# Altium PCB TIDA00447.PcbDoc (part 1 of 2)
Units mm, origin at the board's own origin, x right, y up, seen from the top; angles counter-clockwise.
Board outline 98 x 65 mm, 2 copper layers (Top Layer, Bottom Layer); 127 components, 100 nets, 389 pads, 331 vias.
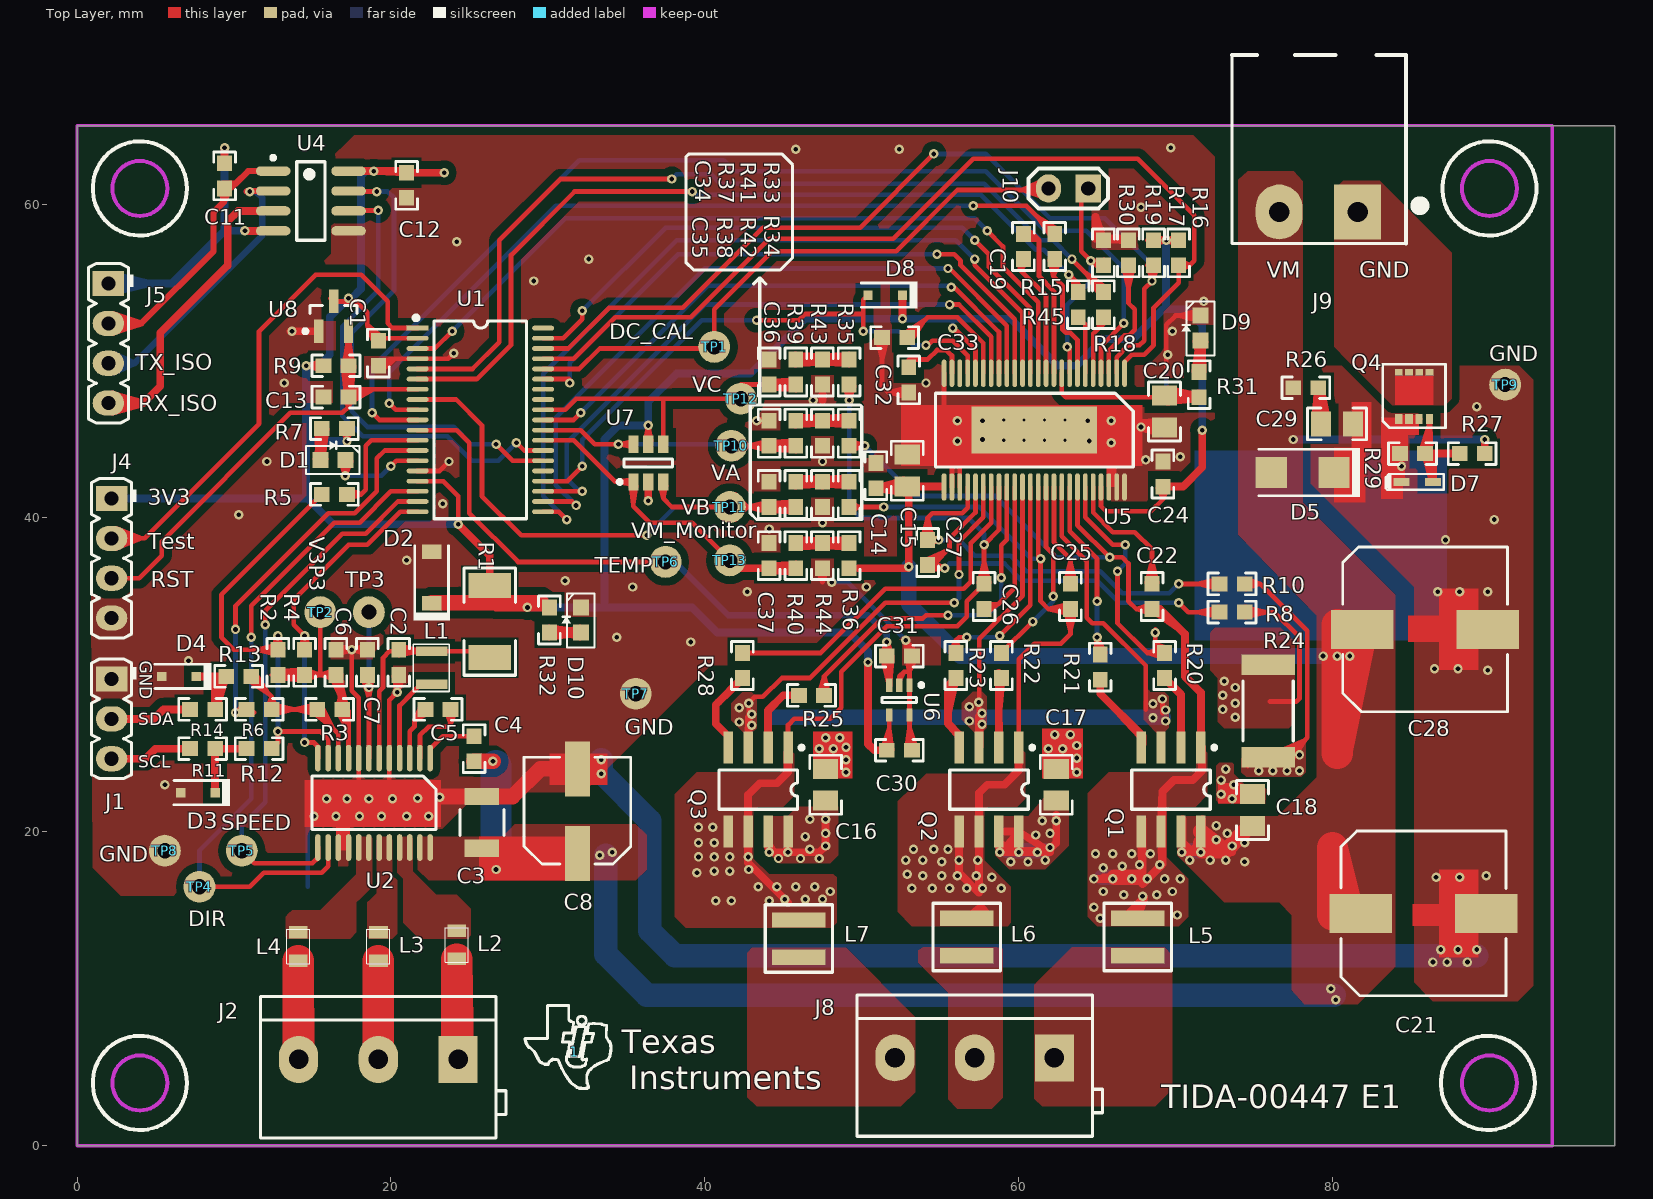
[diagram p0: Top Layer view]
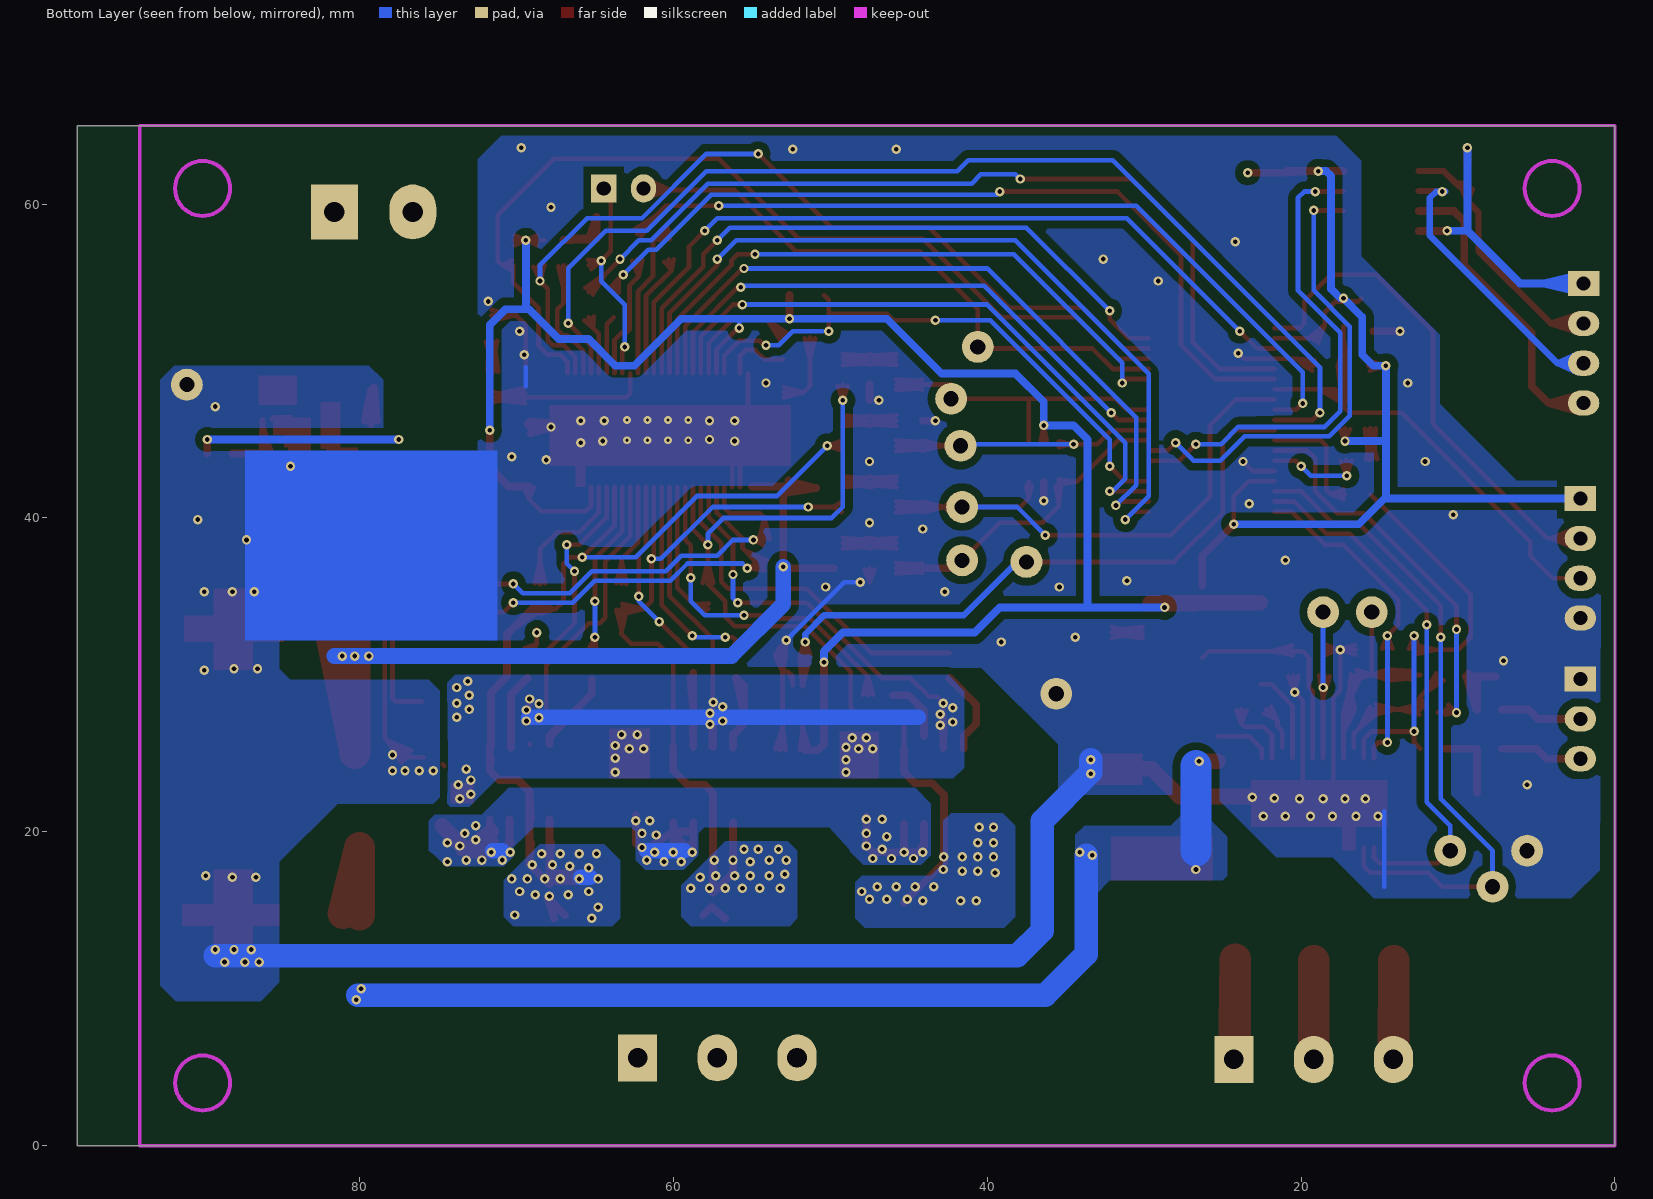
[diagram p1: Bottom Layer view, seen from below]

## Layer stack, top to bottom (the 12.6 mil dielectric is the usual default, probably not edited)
Top Layer: signal copper 0.0356
Dielectric: dielectric 0.32, FR-4, Dk 4.8
Bottom Layer: signal copper 0.0356

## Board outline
0,0 98,0 98,65 0,65

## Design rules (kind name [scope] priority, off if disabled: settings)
Clearance Clearance_1 [(InNamedPolygon('Bottom Layer-GND') OR InNamedPolygon('Bottom Layer-GND2') OR InNamedPolygon('Bottom Layer-GND') OR InNamedPolygon('Top Layer-gnd') OR InNamedPolygon('Top Layer-GND2'))] p1: gap=0.5
Clearance [All] p2: gap=0.2
ComponentClearance [All] p1 off: gap=0.254 collisioncheckmode=3 verticalgap=0.254 showdistances=FALSE
PolygonConnect PolygonConnect_1 [(InPadClass('All Pads'))] p1 off: connectstyle=Relief reliefconductorwidth=0.5 reliefentries=4 polygonreliefangle="90 Angle" airgapwidth=0.5
PolygonConnect [All] p2: connectstyle=Direct reliefconductorwidth=0.254 reliefentries=4 polygonreliefangle="90 Angle" airgapwidth=0.254
RoutingVias [All] p1: holewidth=0.3 width=0.6 viastyle="Through Hole" minholewidth=0.3 minwidth=0.6 maxholewidth=0.3 maxwidth=0.6
SilkscreenOverComponentPads [All] p1: minsilkscreentomaskgap=0.254
SolderMaskExpansion [All] p1: expansion=0.102
Width [All] p1: maxlimit=2 minlimit=0.203 preferedwidth=0.254
26 further rules are at their usual default settings.

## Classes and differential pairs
component class TIDA00447_MCU+DRV10983: C1 C2 C3 C4 C5 C6 C7 C8 C11 C12 C13 D1 D2 D3 D4 J1 J2 J4 J5 L1 L2 L3 L4 R1 R2 R3 R4 R5 R6 R7 R9 R11 R12 R13 R14 TP1 TP2 TP3 TP4 TP5 U1 U2 U4 U8
component class TIDA00447_DRV8303: C8 C14 C15 C16 C17 C18 C19 C20 C21 C22 C24 C25 C26 C27 C29 C30 C31 C32 C33 C34 C35 C36 C37 D5 D7 D8 D9 D10 J8 J9 J10 L5 L6 L7 Q1 Q2 Q3 Q4 R8 R10 R15 R16 R17 R18 R19 R20 R21 R22 R23 R24 R25 R26 R27 R28 R29 R30 R31 R32 R33 R34 R35 R36 R37 R38 R39 R40 R41 R42 R43 R44 R45 TP6 TP7 TP8 TP9 TP10 TP11 TP12 TP13 U5 U6 U7
component class Header: J1 J4 J5

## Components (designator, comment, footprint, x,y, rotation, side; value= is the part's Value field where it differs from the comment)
1 "" TIBUG4 31.7,6 r0 top
C1 "C1608X8R1E104K" 0603 19.2,50.5 r270 top
C2 "C1608X5R1A106M" 0603 20.5,30.8 r270 top
C3 "GRM32ER61H106KA12L" 1210_280 25.8,20.6 r270 top
C4 "C1608X7R1H104K" 0603 25.3,25.3 r90 top
C5 "C1608X7R1H104K" 0603 23,27.8 r180 top
C6 "C1608X5R0J105K" 0603 16.5,30.8 r90 top
C7 "C1608X5R0J105K" 0603 18.5,30.8 r270 top
C8 "APXA6R3ARA101MF60G" CAPSMT_62_F60 31.9,21.3 r90 top (schematic designator C28)
C11 "C1608X8R1E104K" 0603 9.4,61.8 r90 top
C12 "C1608X8R1E104K" 0603 21,61.2 r270 top
C13 "C1608X7R1H222K" 0603 16.5,47.7 r180 top
C14 "06035C104KAT2A" 0603 50.9,42.7 r90 top
C15 "C2012X5R1H475K125AB" 0805_HV 52.9,43.016 r90 top
C16 "C2012X7R1H105K125AB" 0805_HV 47.7,23 r270 top
C17 "C2012X7R1H105K125AB" 0805_HV 62.4,23 r270 top
C18 "C2012X7R1H105K125AB" 0805_HV 74.9,21.4 r270 top
C19 "C1608X8R1H223K" 0603 60.3,57.3 r270 top
C20 "C2012X7R1V225K085AC" 0805_HV 69.3,46.784 r90 top
C21 "EEHZA1V271P" SM_RADIAL_10BMM 85.8,14.8 r0 top
C22 "06035C104KAT2A" 0603 68.5,35 r90 top
C24 "C0603X104K8RACTU" 0603 69.2,42.8 r90 top
C25 "06035C104KAT2A" 0603 63.3,35 r90 top
C26 "06035C104KAT2A" 0603 57.8,35 r270 top
C27 "C1608C0G1H102J" 0603 54.2,37.8 r90 top
C28 "EEHZA1V271P" SM_RADIAL_10BMM 85.9,32.9 r0 top
C29 "08055C103JAT2A" 0805_HV 80.284,46 r0 top
C30 "C1608C0G1E103J" 0603 52.4,25.2 r0 top
C31 "C1608C0G1E103J" 0603 52.4,31.2 r0 top
C32 "C1608X5R1E105K080AC" 0603 53,48.8 r270 top
C33 "C1608X5R1E105K080AC" 0603 52.1,51.5 r180 top
C34 "C1608X5R1A474K" 0603 44.1,45.4 r90 top
C35 "C1608X5R1A474K" 0603 44.1,41.5 r90 top
C36 "C1608X5R1A474K" 0603 44.1,49.3 r90 top
C37 "C1608X5R1A474K" 0603 44.1,37.6 r90 top
D1 "D_LED_603" LED603 16.3,43.7 r180 top
D2 "MMSZ5227B-7-F" SOD-123 22.6,36.2 r90 top
D3 "MMSZ5232BS-7-F" sod-323 7.7,22.5 r180 top
D4 "MMSZ5232BS-7-F" sod-323 6.5,29.9 r180 top
D5 "SMAJ30CA" SMA 78.1,42.9 r180 top
D7 "BZT52C16T-7" SOD-523 85.4,42.3 r180 top
D8 "GBLC03-LF-T7" sod-323 51.5,54.2 r180 top
D9 "D_LED_603" LED603 71.603,52.082 r270 top
D10 "D_LED_603" LED603 32.103,33.482 r270 top
J1 "61300311121" WURTH_61300311121 2.2,27.2 r270 top
J2 "ED120/3DS" CONN_ED120_3DS 19.2,5.5 r270 top
J4 "61300411121" WURTH_61300411121 2.2,37.43 r270 top
J5 "61300411121" WURTH_61300411121 2,51.13 r270 top
J8 "ED120/3DS" CONN_ED120_3DS 57.2,5.6 r270 top
J9 "ED1817-ND" "CN2P/5.0 -11*12" 79.1,59.5 r180 top
J10 "JUMPER_2X100MIL" HDR100_1X2 64.44,61 r180 top
L1 "CB2518T470K" IND_CB2518 22.6,30.45 r270 top
L2 "MPZ2012S300A" MPZ2012 24.2,12.8 r270 top
L3 "MPZ2012S300A" MPZ2012 19.2,12.7 r270 top
L4 "MPZ2012S300A" MPZ2012 14.1,12.7 r270 top
L5 "XFL4015-471MEC" XFL4015 67.6,13.3 r270 top
L6 "XFL4015-471MEC" XFL4015 56.7,13.3 r270 top
L7 "XFL4015-471MEC" XFL4015 46,13.2 r270 top
Q1 "CSD88539ND" SO-G8/E2.5 69.7,22.7 r180 top
Q2 "CSD88539ND" SO-G8/E2.5 58.1,22.7 r180 top
Q3 "CSD88539ND" SO-G8/E2.5 43.4,22.7 r180 top
Q4 "CSD17304Q3" TRANS_NexFET_Q3 85.2,47.8 r90 top
R1 "CRCW20100000Z0EF" 2010 26.3,33.4 r270 top
R2 "CRCW06034K75FKEA" 0603 12.8,30.8 r270 top
R3 "CRCW06034K75FKEA" 0603 16.1,27.8 r0 top
R4 "CRCW06034K75FKEA" 0603 14.5,30.8 r270 top
R5 "RC0603JR-070RL" 0603 16.4,41.5 r180 top
R6 "RC0603JR-070RL" 0603 11.6,27.8 r0 top
R7 "CRCW0603270RJNEA" 0603 16.4,45.7 r0 top
R8 "CRCW06030000Z0EA" 0603 73.6,34 r0 top
R9 "CRCW060347K0JNEA" 0603 16.5,49.7 r180 top
R10 "CRCW06030000Z0EA" 0603 73.6,35.8 r0 top
R11 "CRCW0603100RJNEA" 0603 8,25.3 r0 top
R12 "CRCW0603100RJNEA" 0603 11.6,25.3 r0 top
R13 "CRCW0603100RJNEA" 0603 10.3,29.9 r0 top
R14 "CRCW0603100RJNEA" 0603 8,27.8 r0 top
R15 "CRCW060327R0JNEA" 0603 62.3,57.3 r270 top
R16 "CRCW060310K0FKEA" 0603 70.2,56.9 r90 top
R17 "CRCW060310K0FKEA" 0603 68.6,56.9 r90 top
R18 "CRCW060327R0JNEA" 0603 65.4,53.6 r270 top
R19 "CRCW06031R00FKEA" 0603 67,56.9 r270 top
R20 "CRCW06033R90JNEA" 0603 69.3,30.6 r270 top
R21 "CRCW06033R90JNEA" 0603 65.2,30.5 r270 top
R22 "CRCW06033R90JNEA" 0603 58.9,30.6 r270 top
R23 "CRCW06033R90JNEA" 0603 56,30.6 r270 top
R24 "CSRN2512FK10L0" 2512 75.9,27.7 r90 top
R25 "CRCW06033R90JNEA" 0603 46.8,28.7 r180 top
R26 "CRCW06033R30JNEA" 0603 78.3,48.3 r0 top
R27 "CRCW06033K00JNEA" 0603 88.9,44.1 r0 top
R28 "CRCW06033R90JNEA" 0603 42.4,30.6 r270 top
R29 "CRCW060310K0FKEA" 0603 85.1,44.1 r0 top
R30 "CRCW060310K0FKEA" 0603 65.4,56.9 r270 top
R31 "CRCW06031K00FKEA" 0603 71.5,48.5 r270 top
R32 "CRCW06031K00FKEA" 0603 30.1,33.5 r90 top
R33 "RC0603FR-0730KL" 0603 49.2,45.4 r270 top
R34 "RC0603FR-0730KL" 0603 49.2,41.5 r270 top
R35 "RC0603FR-0730KL" 0603 49.2,49.3 r270 top
R36 "RC0603FR-0730KL" 0603 49.2,37.6 r270 top
R37 "CRCW06031K00FKEA" 0603 45.8,45.4 r270 top
R38 "CRCW06031K00FKEA" 0603 45.8,41.5 r270 top
R39 "CRCW06031K00FKEA" 0603 45.8,49.3 r270 top
R40 "CRCW06031K00FKEA" 0603 45.8,37.6 r270 top
R41 "RC0603FR-073K48L" 0603 47.5,45.4 r90 top
R42 "RC0603FR-073K48L" 0603 47.5,41.5 r90 top
R43 "RC0603FR-073K48L" 0603 47.5,49.3 r90 top
R44 "RC0603FR-073K48L" 0603 47.5,37.6 r90 top
R45 "CRCW060327R0JNEA" 0603 63.8,53.6 r270 top
TP1 "DC_CAL" TESTPOINT 40.6,50.9 r270 top
TP2 "V3P3" TESTPOINT 15.5,34 r270 top
TP3 "V1P8" TESTPOINT 18.6,34 r270 top
TP4 "DIR" TESTPOINT 7.8,16.5 r270 top
TP5 "SPEED" TESTPOINT 10.5,18.8 r270 top
TP6 "TEMP" TESTPOINT 37.5,37.2 r270 top
TP7 "GND" TESTPOINT 35.6,28.8 r270 top
TP8 "GND" TESTPOINT 5.6,18.8 r270 top
TP9 "GND" TESTPOINT 91,48.5 r180 top
TP10 "VA" TESTPOINT 41.7,44.6 r270 top
TP11 "VB" TESTPOINT 41.6,40.7 r270 top
TP12 "VC" TESTPOINT 42.3,47.6 r270 top
TP13 "VM_Monitor" TESTPOINT 41.6,37.3 r270 top
U1 "MSP430G2544_DA_3" IC-TSSOP38-DA 25.7,46.25 r0 top
U2 "DRV10983PWP" PWP0024B_N 18.925,21.85 r270 top
U4 "ISO7421D" D0008A_N 14.9,60.2 r0 top
U5 "DRV8303DCA" DCA0048A_N 61,45.6 r270 top
U6 "LMT84DCK" DCK0005A_N 52.4,28.4 r270 top
U7 "TPD4S009DBVRG4" DBV0006A_N 36.4,43.5 r90 top
U8 "TLV803SDBZR" DBZ0003A_N 16.35,52.85 r90 top

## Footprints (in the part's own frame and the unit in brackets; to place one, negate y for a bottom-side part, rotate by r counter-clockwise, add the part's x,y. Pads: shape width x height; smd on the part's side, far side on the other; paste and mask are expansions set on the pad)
0603 [mm] "0603 from SM-752 data"
  rect 1x0.95 smd: 1(-0.8,0) 2(0.8,0)
  silkscreen extent -1.52,-0.69 1.52,0.69, body extent -0.87,-0.47 0.87,0.47, height 0.85
0805_HV [mil] "0805 with 30mil clearance between pads"
  rect 50x63 smd: 1(-40,0) 2(40,0)
  silkscreen extent -74,-40 74,40, body extent -43,-29 43,29, height 43
1210_280 [mm] "SMD, 2-Leads, Body 3.6x2.8mm, Height 2.8mm"
  rect 1.1x2.2 smd: 1(-1.65,0) 2(1.65,0)
  silkscreen extent -0.84,-1.4 0.84,1.4, body extent -1.8,-1.4 1.8,1.4, height 2.8
2010 [mm] "Chip Capacitor, Body 5.08x2.54mm, IPC Medium Density"
  rect 1.6x2.7 smd: 1(-2.3,0) 2(2.3,0)
  silkscreen extent -3.42,-1.65 3.42,1.65, body extent -2.73,-1.45 2.73,1.45, height 1.66
2512 [mm] "Chip Resistor, Body 6.3x3.2mm, IPC Medium Density"
  rect 1.3x3.4 smd: 1(-2.95,0) 2(2.95,0)
  silkscreen extent -1.9,-1.6 1.9,1.6, body extent -3.22,-1.67 3.22,1.67, height 0.71
CAPSMT_62_F60 [mm] "6.3 x 5.7mm:  Chemi-Con F60"
  rect 3.5x1.6 smd: 1(-2.688,0.012) 2(2.712,0.012)
  silkscreen extent -3.35,-3.39 3.45,3.41, body extent -3.4,-3.4 3.45,3.42, height 6
"CN2P/5.0 -11*12" [mm]
  rect 3x3.5 hole 1.3: 1(-2.5,0)
  oval 3x3.5 hole 1.3: 2(2.5,0)
  silkscreen extent -6.57,-10 5.5,2
CONN_ED120_3DS [mm] "ONSHORE"
  rect 3x2.5 hole 1.25: 1(0,5.08)
  oval 3x2.5 hole 1.25: 2(0,0) 3(0,-5.08)
  silkscreen extent -4,-7.5 5,8.14, body extent -4.13,-7.55 5.05,8.14, height 13.1
D0008A_N [mm] "SOIC, 8-Leads, Body 4.9x3.9mm, Pitch 1.27mm, IPC Medium Density"
  oval 2.2x0.6 smd: 1(-2.4,1.905) 2(-2.4,0.635) 3(-2.4,-0.635) 4(-2.4,-1.905) 5(2.4,-1.905) 6(2.4,-0.635) 7(2.4,0.635) 8(2.4,1.905)
  silkscreen extent -2.52,-2.5 0.9,2.88, body extent -2,-2.5 2,2.5, height 1.75
DBV0006A_N [mm] "SOT23, 6-Leads, Body 2.9x1.6mm, Pitch 0.95mm, Lead Span 2.8mm, IPC Medium Density"
  rect 1.1x0.65 smd: 1(-1.2,0.95) 2(-1.2,0) 3(-1.2,-0.95) 4(1.2,-0.95) 5(1.2,0) 6(1.2,0.95)
  silkscreen extent -1.32,-1.55 0.25,1.95, body extent -0.87,-1.52 0.87,1.53, height 1.45
DBZ0003A_N [mm] "SOT23, 3-Leads, Body 2.9x1.3mm, Pitch 0.95mm, Lead Span 2.4mm, IPC Medium Density"
  rect 1.5x0.6 smd: 1(-0.95,0.95) 2(-0.95,-0.95) 3(0.95,0)
  silkscreen extent -1.07,-1.5 0.7,1.92, body extent -0.7,-1.52 0.7,1.52, height 1.12
DCA0048A_N [mm] "TSSOP, 48-Leads, Body 12.6x6.2mm (max), Pitch 0.50mm, IPC Medium Density"
  oval 1.75x0.3 smd: 1(-3.625,5.75) 2(-3.625,5.25) 3(-3.625,4.75) 4(-3.625,4.25) 5(-3.625,3.75) 6(-3.625,3.25) 7(-3.625,2.75) 8(-3.625,2.25) 9(-3.625,1.75) 10(-3.625,1.25) 11(-3.625,0.75) 12(-3.625,0.25) 13(-3.625,-0.25) 14(-3.625,-0.75) 15(-3.625,-1.25) 16(-3.625,-1.75) 17(-3.625,-2.25) 18(-3.625,-2.75) 19(-3.625,-3.25) 20(-3.625,-3.75) 21(-3.625,-4.25) 22(-3.625,-4.75) 23(-3.625,-5.25) 24(-3.625,-5.75) 25(3.625,-5.75) 26(3.625,-5.25) 27(3.625,-4.75) 28(3.625,-4.25) 29(3.625,-3.75) 30(3.625,-3.25) 31(3.625,-2.75) 32(3.625,-2.25) 33(3.625,-1.75) 34(3.625,-1.25) 35(3.625,-0.75) 36(3.625,-0.25) 37(3.625,0.25) 38(3.625,0.75) 39(3.625,1.25) 40(3.625,1.75) 41(3.625,2.25) 42(3.625,2.75) 43(3.625,3.25) 44(3.625,3.75) 45(3.625,4.25) 46(3.625,4.75) 47(3.625,5.25) 48(3.625,5.75)
  rect 3x8 smd: 49(0,0)
  silkscreen extent -2.35,-6.3 2.35,6.3, body extent -4.06,-6.25 4.06,6.25, height 0.98
DCK0005A_N [mm] "SOT353, 5-Leads, Body 2x1.3mm, Pitch 0.65mm, Lead Span 2.1mm, IPC Medium Density"
  rect 0.85x0.4 smd: 1(-0.95,0.65) 2(-0.95,0) 3(-0.95,-0.65) 4(0.95,-0.65) 5(0.95,0.65)
  silkscreen extent -1.07,-1.1 0.15,1.53, body extent -0.7,-1.07 0.7,1.08, height 1.1
HDR100_1X2 [mm]
  rect 1.6x1.8 hole 0.9: 1(0,0)
  oval 1.6x1.8 hole 0.9: 2(2.54,0)
  silkscreen extent -1.27,-1.27 3.81,1.27
IC-TSSOP38-DA [mm]
  rect 1.4x0.3 smd: 1(-4,5.85)
  oval 1.4x0.3 smd: 2(-4,5.2) 3(-4,4.55) 4(-4,3.9) 5(-4,3.25) 6(-4,2.6) 7(-4,1.95) 8(-4,1.3) 9(-4,0.65) 10(-4,0) 11(-4,-0.65) 12(-4,-1.3) 13(-4,-1.95) 14(-4,-2.6) 15(-4,-3.25) 16(-4,-3.9) 17(-4,-4.55) 18(-4,-5.2) 19(-4,-5.85) 20(4,-5.85) 21(4,-5.2) 22(4,-4.55) 23(4,-3.9) 24(4,-3.25) 25(4,-2.6) 26(4,-1.95) 27(4,-1.3) 28(4,-0.65) 29(4,0) 30(4,0.65) 31(4,1.3) 32(4,1.95) 33(4,2.6) 34(4,3.25) 35(4,3.9) 36(4,4.55) 37(4,5.2) 38(4,5.85)
  silkscreen extent -4.25,-6.3 2.95,6.65
IND_CB2518 [mm] "TAIYO YUDEN"
  rect 0.6x2 smd: 1(-1.05,0) 2(1.05,0)
  silkscreen extent -1.49,-1.17 1.51,1.13, body extent -1.35,-1 1.35,1, height 2
LED603 [mil]
  rect 40x40 smd: 1(-32.2,-0.1) 2(30.8,-0.1)
  silkscreen extent -67,-47 68,35
MPZ2012 [mm] "MURATA"
  rect 0.8x1.2 smd: 1(-0.9,0) 2(0.9,0)
  silkscreen extent -1.1,-0.72 1.1,0.72, body extent -1.1,-0.72 1.1,0.72, height 1.05
PWP0024B_N [mm] "TSOP, 24-Leads, Body 7.9x4.5mm (max), Pitch 0.65mm, IPC Medium Density"
  oval 1.7x0.35 smd mask+0.085: 1(-2.85,3.575) 2(-2.85,2.925) 3(-2.85,2.275) 4(-2.85,1.625) 5(-2.85,0.975) 6(-2.85,0.325) 7(-2.85,-0.325) 8(-2.85,-0.975) 9(-2.85,-1.625) 10(-2.85,-2.275) 11(-2.85,-2.925) 13(2.85,-3.575) 14(2.85,-2.925) 15(2.85,-2.275) 16(2.85,-1.625) 17(2.85,-0.975) 18(2.85,-0.325) 19(2.85,0.325) 20(2.85,0.975) 21(2.85,1.625) 22(2.85,2.275) 23(2.85,2.925) 24(2.85,3.575)
  oval 1.7x0.35 smd: 12(-2.85,-3.575)
  silkscreen extent -1.7,-3.95 1.7,3.95, body extent -3.21,-3.9 3.21,3.9, height 0.98
SM_RADIAL_10BMM [mm] "Nichicon 10x10"
  rect 4x2.5 smd: 1(-4,0) 2(4,0)
  silkscreen extent -5.25,-5.25 5.25,5.25, body extent -5.26,-5.26 5.26,5.26, height 10.5
SMA [mm] "Molded Diode, 2-Leads, Body 4.3x2.6mm, IPC Medium Density, based on OnSemi component dimensions and land pattern"
  rect 2x2 smd: 1(-2,0) 2(2,0)
  silkscreen extent -3.66,-1.57 2.79,1.57, body extent -2.6,-1.3 2.6,1.3, height 2.42
SO-G8/E2.5 [mm]
  rect 0.6x2.05 smd: 1(-1.915,-2.666) 2(-0.645,-2.666) 3(0.625,-2.666) 4(1.895,-2.666) 5(1.895,2.684) 6(0.625,2.684) 7(-0.645,2.684) 8(-1.915,2.684)
  silkscreen extent -2.89,-2.79 2.49,1.26
SOD-123 [mm] "On Semi recommended land pattern"
  rect 0.915x1.22 smd: 1(-1.637,0) 2(1.637,0)
  silkscreen extent -2.74,-1.17 2.03,1.17, body extent -1.93,-0.9 1.93,0.9, height 1.35
sod-323 [mm] "NXP recommended land pattern"
  rect 0.6x0.6 smd paste-0.05: 1(-1.1,0) 2(1.1,0)
  silkscreen extent -2.06,-0.86 1.53,0.86, body extent -1.3,-0.67 1.3,0.68, height 1.1
SOD-523 [mm]
  rect 1x0.5 smd: 1(-1,0) 2(1,0)
  silkscreen extent -1.7,-0.5 2,0.5
TESTPOINT [mil]
  round 80 hole 37.99: 1(0,0)
TIBUG4 [mm]
  silkscreen extent -3.15,-2.35 2.32,2.93
TRANS_NexFET_Q3 [mm] "TI recommended land pattern (nominal) M0143-01"
  rect 0.63x0.5 smd mask+0.076: 1(-1.49,0.975) 2(-1.49,0.325)
  rect 0.63x0.45 smd mask+0.076: 3(-1.49,-0.325) 4(-1.49,-0.975)
  rect 0.41x0.5 smd mask+0.076: 5(1.49,-0.975) 6(1.49,-0.325) 7(1.49,0.325) 8(1.49,0.975)
  Top Layer region: -0.615,-1.225 1.285,-1.225 1.285,1.225 -0.615,1.225
  silkscreen extent -2.05,-2 2,2, body extent -1.76,-1.7 1.66,1.7, height 1.11
WURTH_61300311121 [mm] "Header, 2.54mm, 3x1, TH"
  rect 1.6x2 hole 0.9: 1(-2.54,0)
  oval 1.6x2 hole 0.9: 2(0,0) 3(2.54,0)
  silkscreen extent -3.81,-1.27 3.81,1.6, body extent -3.81,-1.27 3.81,1.27, height 8.54
WURTH_61300411121 [mm] "Header, 2.54mm, 4x1, TH"
  rect 1.6x2 hole 0.9: 1(-3.81,0)
  oval 1.6x2 hole 0.9: 2(-1.27,0) 3(1.27,0) 4(3.81,0)
  silkscreen extent -5.08,-1.27 5.08,1.6, body extent -5.08,-1.27 5.08,1.27, height 8.54
XFL4015 [mm] "SMD, 2-Leads, Body 4x4mm"
  rect 0.98x3.4 smd: 1(-1.185,0) 2(1.185,0)
  silkscreen extent -2.15,-2.15 2.15,2.15, body extent -2.15,-2.15 2.15,2.15, height 1.6

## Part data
C1 C11 C12: "CAP, CERM, 0.1 μF, 25 V, +/- 10%, X8R, 0603"
C2: "CAP, CERM, 10 μF, 10 V, +/- 20%, X5R, 0603"
C3: "CAP, CERM, 10 μF, 50 V, +/- 10%, X5R, 1210"
C4 C5 C14 C22 C25 C26: "CAP, CERM, 0.1 μF, 50 V, +/- 10%, X7R, 0603"
C6 C7: "CAP, CERM, 1 μF, 6.3 V, +/- 10%, X5R, 0603"
C8: "CAP, AL, 100uF, 6.3V, +/-20%, 0.027 ohm, SMD"
C13: "CAP, CERM, 2200 pF, 50 V, +/- 10%, X7R, 0603"
C15: "CAP, CERM, 4.7 μF, 50 V, +/- 10%, X5R, 0805"
C16 C17 C18: "CAP, CERM, 1 μF, 50 V, +/- 10%, X7R, 0805"
C19: "CAP, CERM, 0.022 μF, 50 V, +/- 10%, X8R, 0603"
C20: "CAP, CERM, 2.2 μF, 35 V, +/- 10%, X7R, 0805"
C21 C28: "CAP, AL, 270 μF, 35 V, +/- 20%, 20 ohm, SMD"
C24: "CAP, CERM, 0.1 μF, 10 V, +/- 10%, X7R, 0603"
C27: "CAP, CERM, 1000 pF, 50 V, +/- 5%, C0G/NP0, 0603"
C29: "CAP, CERM, 0.01 μF, 50 V, +/- 5%, X7R, 0805"
C30 C31: "CAP, CERM, 0.01 μF, 25 V, +/- 5%, C0G/NP0, 0603"
C32 C33: "CAP, CERM, 1 μF, 25 V, +/- 10%, X5R, 0603"
C34 C35 C36 C37: "CAP, CERM, 0.47 μF, 10 V, +/- 10%, X5R, 0603"
D1 D9 D10: "Diode, LED, [Color], x-V, 20-mA, y-mcd"
D2: "Diode, Zener, 3.6 V, 500 mW, SOD-123"
D3 D4: "Diode, Zener, 5.6 V, 200 mW, SOD-323"
D5: "Diode, TVS, Bi, 30 V, 400 W, SMA"
D7: "Diode, Zener, 16 V, 300 mW, SOD-523"
D8: "Diode, TVS, Uni, 3.3 V, 350 W, SOD-323"
J1: "Header, 2.54 mm, 3x1, Gold, TH"
J2 J8: "TERMINAL BLOCK 5.08MM VERT 3POS, TH"
J4 J5: "Header, 2.54 mm, 4x1, Gold, TH"
J9: library part ED120/2DS, "TERMINAL BLOCK 5.08MM VERT 2POS, TH"
J10: "Header, Male 2-pin, 100mil spacing,"
L1: "Inductor, Wirewound, Ferrite, 47 μH, 0.11 A, 1.235 ohm, SMD"
L2 L3 L4: library part MPZ2012S101A, "Ferrite Bead, 100 ohm @ 100 MHz, 4 A, 0805"
L5 L6 L7: "Inductor, Shielded, Composite, 470 nH, 3.5 A, 0.0076 ohm, SMD"
Q1 Q2 Q3: "MOSFET, N-CH, 60 V, 6.3 A, SO-8"
Q4: "MOSFET, N-CH, 30 V, 56 A, SON 3.3x3.3mm"
R1: "RES, 0, 5%, 0.75 W, 2010"
R2 R3 R4: "RES, 4.75 k, 1%, 0.1 W, 0603"
R5 R6 R8 R10: "RES, 0, 5%, 0.1 W, 0603"
R7: "RES, 270, 5%, 0.1 W, 0603"
R9: "RES, 47 k, 5%, 0.1 W, 0603"
R11 R12 R13 R14: "RES, 100, 5%, 0.1 W, 0603"
R15 R18 R45: "RES, 27, 5%, 0.1 W, 0603"
R16 R17 R29 R30: "RES, 10.0 k, 1%, 0.1 W, 0603"
R19: "RES, 1.00, 1%, 0.1 W, 0603"
R20 R21 R22 R23 R25 R28: "RES, 3.9, 5%, 0.1 W, 0603"
R24: "RES, 0.01, 1%, 2 W, 2512"
R26: "RES, 3.3, 5%, 0.1 W, 0603"
R27: "RES, 3.0 k, 5%, 0.1 W, 0603"
R31 R32 R37 R38 R39 R40: "RES, 1.00 k, 1%, 0.1 W, 0603"
R33 R34 R35 R36: "RES, 30.0 k, 1%, 0.1 W, 0603"
R41 R42 R43 R44: "RES, 3.48 k, 1%, 0.1 W, 0603"
TP1 TP2 TP3 TP4 TP5 TP6 TP7 TP8 TP9 TP10 TP11 TP12 TP13: library part TESTPOINT, "TEST POINT.  No entry in BOM."
U1: "Imported"
U2: "12- to 24-V, Three-Phase, Sensorless BLDC Motor Driver, PWP0024B"
U4: "1 Mbps Dual Channels, 1 / 1, Digital Isolator, 3.3 V / 5 V, -40 to +105 degC, 8-pin SOIC (D), Green (RoHS & no Sb/Br)"
U5: "THREE PHASE PRE-DRIVER WITH DUAL CURRENT SHUNT AMPLIFIERS, DCA0048A"
U6: "Analog Temperature Sensors with Class-AB Output, DCK0005A"
U7: "ESD Solution for High-Speed Differential Interface, 4 Channels, -40 to +85 degC, 6-pin SOT-23 (DBV), Green (RoHS & no Sb/Br)"
U8: "3-Pin Voltage Supervisors with Active-Low, Open-Drain Reset, DBZ0003A"

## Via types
v1: diameter 0.6, hole 0.3, Top Layer to Bottom Layer, 323 vias
v2: diameter 0.5, hole 0.2, Top Layer to Bottom Layer, tented top, 8 vias

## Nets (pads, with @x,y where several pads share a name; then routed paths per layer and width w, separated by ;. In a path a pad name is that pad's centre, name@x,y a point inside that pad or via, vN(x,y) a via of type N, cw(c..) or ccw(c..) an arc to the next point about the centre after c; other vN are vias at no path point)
3V3_ISO: C11.1 J5.2 U4.1 | length 27.5
  Top Layer w0.4: J5.2@2,52.4 4.1,52.4 ; J5.2@2.2,52.4 4.1,52.4 ; J5.2@2.295,51.808 4.1,52.4 ; J5.2@2.295,52.992 4.1,52.4 ; C11.1@9.129,60.926 9.4,60.2 ; C11.1@9.348,61.295 10.1,61.3 ; C11.1@9.4,60.975 9.4,60.2 ; C11.1@9.4,61.025 10.1,61.3 ; C11.1@9.546,60.792 10.1,61.3 ; C11.1@9.671,60.926 9.4,60.2 ; U4.1@11.7,62.105 10.905,62.105 ; U4.1@12.5,62.105 10.905,62.105 ; 4.1,52.4 8.7,57 8.7,59.5 9.4,60.2 ; 9.4,60.2 C11.1@9.4,61 9.7,61.3 10.1,61.3 ; 10.1,61.3 10.905,62.105
GND: C1.2 C2.2 C3.1 C6.2 C7.1 C8.2 C12.2 C13.2 C14.2 C15.2 C20.1 C21.2 C24.2 C28.2 C29.2 C30.2 C31.2 C32.2 C33.2 C34.2 C35.2 C36.2 C37.2 D2.2 D3.2 D4.2 D5.1 D7.2 D9.1 D10.1 J1.1 J4.4 Q4.1 Q4.2 Q4.3 R10.2 R19.1 R24.1 R29.1 R30.1 R41.1 R42.1 R43.1 R44.1 TP7.1 TP8.1 TP9.1 U1.4 U1.15 U2.5 U2.8 U2.15 U2.16 U4.5 U5.24 U5.26 U5.27 U5.46 U5.47 U5.48 U5.49 U6.1 U6.2 U6.5 U7.2 U8.1 | length 311.7
  Top Layer w0.3: C6.2@16.5,31.6 v1@17.6,31.6 ; C6.2@16.548,31.279 v1@17.6,31.6 ; C6.2@16.548,31.921 v1@17.6,31.6 ; C6.2@16.6,31.6 v1@17.6,31.6 ; 17.95,22.35 U2.8@17.95,24.7 17.95,28.55 17.5,29 17.5,31.5 v1@17.6,31.6 ; 17.95,22.95 U2.8@17.95,24.025 ; U2.8@17.95,25.375 17.95,26.45 ; C7.1@18.441,31.28 v1@17.6,31.6 ; C7.1@18.441,31.92 v1@17.6,31.6 ; C7.1@18.5,31.6 v1@17.6,31.6 ; C1.2@19.123,50.041 20.25,50.15 ; C1.2@19.2,49.725 20.25,50.15 ; C1.2@19.364,49.444 20.25,50.15 ; 19.9,22.5 U2.5@19.9,24.7 19.9,28.4 v1(20.4,28.9) ; 19.9,22.95 U2.5@19.9,24.025 ; U2.5@19.9,25.375 19.9,26.45 ; C2.2@20.176,29.956 v1(20.4,28.9) ; C2.2@20.4,29.6 v1(20.4,28.9) ; C2.2@20.5,29.975 v1(20.4,28.9) ; C2.2@20.815,29.897 v1(20.4,28.9) ; U1.4@21.15,50.15 20.25,50.15 ; U1.15@21.7,43 23.1,43 ; U1.15@22.25,43 23.1,43 ; U1.4@22.25,50.15 23.3,50.15 ; v1(23.7,43.6) 23.1,43 ; v1(24,50.5) 23.65,50.15 U1.4@21.7,50.15 20.25,50.15 ; R44.1@47.181,36.715 47.5,35.9 ; R44.1@47.5,36.775 47.5,35.9 ; R44.1@47.5,36.8 47.5,35.9 ; R44.1@47.819,36.715 47.5,35.9 ; C33.2@50.977,51.462 51.3,50.125 C33.2@51.623,51.462 ; C33.2@51.3,51.5 51.3,48.4 51.7,48 ; U6.2@52.4,29.35 52.4,29.9 ; C15.2@52.684,43.784 52.75,43.85 55.95,43.85 ; C30.2@52.85,25.209 53.05,26.596 ; C31.2@52.85,31.188 53.05,30.2 ; C31.2@52.857,31.134 v1(52.8,32.2) ; C32.2@52.959,47.678 51.7,48 ; C32.2@52.959,48.322 51.7,48 ; C32.2@53,48 51.7,48 ; 53.05,26.125 U6.5@53.05,27.225 ; U6.5@53.05,27.675 53.05,28.775 U6.1@53.05,29.125 ; U6.1@53.05,29.575 53.05,30.2 ; C15.2@53.054,43.847 54.61,43.85 ; C15.2@53.065,44.032 54.61,43.85 ; C15.2@53.084,43.547 54.61,43.85 ; C15.2@53.098,44.214 54.61,43.85 ; C30.2@53.175,25.2 53.05,26.596 ; C15.2@53.196,44.499 54.61,43.85 ; C30.2@53.2,25.2 53.05,25.35 U6.5@53.05,27.45 U6.1@53.05,29.35 53.05,30.2 ; C31.2@53.458,31.359 v1(52.8,32.2) ; C31.2@53.487,31.108 53.05,30.2 ; C30.2@53.493,25.266 53.05,26.596 ; U5.24@55.225,49.2 U5.24@55.25,49.225 55.25,46.15 55.8,45.6 U5.49@58.5,45.6 ; 55.25,47.45 U5.24@55.25,48.5 ; U5.26@55.75,41.975 55.75,43.65 ; U5.26@55.75,42.7 55.75,43.65 ; U5.27@56.25,41.975 56.25,43.65 ; U5.27@56.25,42.7 56.25,43.65 ; U5.49@59.834,44.261 U5.49@58.5,45.6 ; U5.49@59.834,46.939 U5.49@58.5,45.6 ; U5.49@60.04,44.505 U5.49@58.5,45.6 ; U5.49@60.04,46.695 U5.49@58.5,45.6 ; U5.49@60.199,44.772 U5.49@58.5,45.6 ; U5.49@60.199,46.428 U5.49@58.5,45.6 ; U5.49@60.31,45.056 U5.49@58.5,45.6 ; U5.49@60.31,46.144 U5.49@58.5,45.6 ; U5.49@60.373,45.351 U5.49@58.5,45.6 ; U5.49@60.373,45.849 U5.49@58.5,45.6 ; U5.49@60.39,45.6 U5.49@58.5,45.6 ; U5.49@61,45.6 U5.49@58.5,45.6 ; 69.4,49.6 69.4,52.3 70,52.9 D9.1@71.6,52.9 70.192,52.9 ; D9.1@71.554,52.545 70.192,52.9 ; D9.1@71.554,53.255 70.192,52.9 ; R10.2@74.4,35.8 75.4,35.8 ; R10.2@74.425,35.8 75.4,35.8 ; R10.2@74.479,35.48 75.4,35.8 ; R10.2@74.479,36.12 75.4,35.8 ; R24.1@74.6,24.2 R24.1@74.7,24.3 ; R24.1@75.9,24.75 77.15,24.75 78.4,26 78.4,32.8 75.4,35.8 ; R24.1@76.687,25.175 78.247,25.847 ; R24.1@76.83,24.91 78.247,25.847 ; R24.1@76.95,24.75 78.247,25.847 ; R24.1@77.088,24.605 78.247,25.847 ; R24.1@77.326,24.42 78.247,25.847 ; D7.2@84.3,42.4 D7.2@84.4,42.3 ; 19.8,49.7 19.288,49.387 19.8,49.7 ; 19.8,49.7 19.288,50.013 19.8,49.7 ; 19.8,49.7 C1.2@19.2,49.7 19.8,49.7 ; 19.8,49.7 20.25,50.15 ; U6.2@52.4,29.575 52.4,29.9 ; U6.2@52.4,29.575 52.4,29.9 ; U6.2@52.4,29.575 52.7,30.2 ; 52.4,29.9 52.7,30.2 ; 52.7,30.2 53.05,30.2 ; v1(52.8,32.2) 53.175,31.2 53.05,30.2 ; v1(52.8,32.2) 53.2,31.8 ; U6.1@53.05,29.125 53.05,28.025 U6.1@53.05,29.125 ; 53.05,30.2 53.05,31.05 C31.2@53.2,31.2 ; C31.2@53.2,31.2 53.2,31.8 ; C31.2@53.2,31.2 53.2,31.8 ; 53.2,31.8 53.513,31.288 53.2,31.8 ; 53.2,31.8 52.887,31.288 53.2,31.8 ; 55.75,43.65 55.95,43.85 ; 55.95,43.85 56.45,43.85 ; 56.25,43.65 56.45,43.85 ; 56.45,43.85 56.75,43.85 U5.49@58.5,45.6
  Top Layer w0.4: Q4.2@84.875,46.31 Q4.3@85.525,46.31 Q4.2@84.875,46.31
  Top Layer w0.5: v1@13.6,51.9 v1(13.7,51.9) ; U7.2@36.4,42.075 v1(36.4,41.1) U7.2@36.4,42.3 ; R43.1@47.5,48.475 47.5,47.5 R43.1@47.5,48.5 ; R30.1@65.019,57.8 R19.1@67,57.725 ; 66.716,45.984 C20.1@69.3,45.984 ; C20.1@69.062,45.39 66.986,45.984 ; C20.1@69.135,45.768 66.986,45.984 ; C20.1@69.139,46.153 66.986,45.984 ; R29.1@84.3,44.073 D7.2@84.4,42.3 R29.1@84.3,44.074 ; R29.1@84.3,44.1 84.3,42.4 R29.1@84.3,44.4 ; v1(13.7,51.9) U8.1@15.4,51.9 v1(13.7,51.9) ; 64.9,57.8 R30.1@65.4,57.725 ; 64.9,57.8 R30.1@65.4,57.725 ; 64.9,57.8 66.4,57.8 ; 64.9,57.8 64.9,59.2 R30.1@65.4,57.725 ; R30.1@65.4,57.725 R19.1@67,57.7 66.5,57.7 66.4,57.8 ; R30.1@65.4,57.725 66.4,57.8 ; 66.4,57.8 R19.1@67,57.725 ; 66.4,57.8 R19.1@67,57.725 ; 66.4,57.8 R19.1@67,57.725 ; v1(43.3,46.2) C34.2@44.1,46.2 v1(43.3,46.2)
  Top Layer w1: 20.75,22.25 C3.1@25.8,22.25 27.75,22.25 ; v1@21.7,22.25 C3.1@25.25,22.25 ; C3.1@26.35,22.25 27.75,22.25 ; C8.2@31.888,24.012 29.512,24.012 27.75,22.25
  Bottom Layer w0.3: 14.7,16.5 14.7,21.3 ; v1(48.1,35.9) 49.1,35.9 v1(52.8,32.2) ; 69.4,48.4 69.4,49.6
  Bottom Layer w1.5: v1(33.4,24.6) 33.4,23.8 36.5,20.7 36.5,13.7 38.1,12.1 89.2,12.1
  other v1: 86.4,11.7 87.3,11.7 88.6,11.7 86.9,12.5 88,12.5 89.2,12.5 86.6,17.1 88.1,17.1 89.8,17.2 15.1,21 16.5,21 18,21 19.4,21 21,21 22.4,21 15.9,22.1 17.2,22.1 18.6,22.1 20.1,22.1 21.7,22.15 23.1,22.2 5.6,23 33.4,23.7 75.3,23.9 76.2,23.9 77.1,23.9 77.9,23.9 77.9,24.9 89.9,30.3 86.5,30.4 88,30.4 7.1,30.9 17.5,31.6 39.1,32.1 34.4,32.4 42.7,35.3 86.7,35.3 88.1,35.3 89.9,35.3 35.4,35.6 50.3,35.6 31.1,36 21,37.3 87.2,38.6 44.1,39.3 47.5,39.7 90.3,39.9 10.3,40.2 23.3,40.9 84.4,43.3 12.1,43.6 47.5,43.6 68.1,43.7 70.3,43.9 65.9,44.8 56.1,44.9 64.5,44.9 57.7,45 67.8,45.8 56.1,46.2 57.7,46.2 64.4,46.2 65.9,46.2 89.2,47.1 46.9,47.5 13.2,48.6 54.1,48.6 69.5,50.4 69.8,51.9 71.8,53.8 29.1,55.1 32.6,56.5 24.2,57.6 67.8,59.8 45.8,63.5 52.4,63.5 69.7,63.6
  other v2: 59.05,44.95 60.35,44.95 61.65,44.95 62.95,44.95 59.05,46.25 60.35,46.25 61.65,46.25 62.95,46.25
GND_IN: J9.1 Q4.5 Q4.6 Q4.7 Q4.8
GVDD: C20.2 R31.2 U5.9 | length 56.1
  Top Layer w0.3: U5.9@62.75,48.5 62.75,47.95 ; U5.9@62.75,49.225 62.75,47.95 ; C20.2@69.439,47.617 70.992,47.491 ; C20.2@69.444,47.315 70.992,47.491 ; C20.2@69.461,47.985 R31.2@71.08,47.931 ; C20.2@69.491,47.617 R31.2@71.08,47.931 ; C20.2@69.499,48.284 R31.2@71.08,47.931 ; C20.2@69.513,47.979 70.992,47.491 ; C20.2@69.576,47.328 R31.2@71.08,47.931 ; C20.2@69.634,48.255 70.992,47.491 ; R31.2@71.462,47.377 70.125,47.7 ; R31.2@71.462,48.023 70.125,47.7 ; 62.75,47.95 63,47.7 R31.2@71.5,47.7 70.125,47.7 ; C20.2@69.463,47.615 70.125,47.7 ; C20.2@69.463,47.615 70.125,47.7 ; C20.2@69.463,47.615 70.125,47.7 ; C20.2@69.465,47.8 71.003,47.7 ; C20.2@69.465,47.8 70.125,47.7 ; C20.2@69.465,47.8 71.003,47.7 ; C20.2@69.465,47.8 70.125,47.7 ; C20.2@69.465,47.8 R31.2@71.08,47.931 ; C20.2@69.465,47.8 70.125,47.7 ; C20.2@69.465,47.8 70.992,47.491 ; C20.2@69.518,47.977 70.125,47.7 ; C20.2@69.518,47.977 70.125,47.7 ; C20.2@69.518,47.977 70.125,47.7 ; C20.2@69.572,47.327 70.125,47.7 ; C20.2@69.572,47.327 70.125,47.7 ; C20.2@69.572,47.327 70.125,47.7 ; C20.2@69.707,48.22 70.125,47.7 ; C20.2@69.707,48.22 70.125,47.7 ; C20.2@69.707,48.22 70.125,47.7 ; 71.003,47.7 69.464,47.615 71.003,47.7 ; 71.003,47.7 69.488,47.984 71.003,47.7 ; 71.003,47.7 69.51,47.317 71.003,47.7 ; 71.003,47.7 69.572,48.273 71.003,47.7
M1_BEMF_VA: C34.1 R37.2 TP10.1 U1.28 U7.6 | length 67.1
  Top Layer w0.3: U1.28@29.7,45.6 32.1,45.6 33,44.7 v1(34.5,44.7) ; U1.28@30.25,45.6 31.3,45.6 ; U7.6@35.406,44.531 35.1,44.7 ; U7.6@35.406,44.869 35.1,44.7 ; TP10.1@41.6,45.3 42.3,44.6 C34.1@44.1,44.6 ; C34.1@44.062,44.277 42.725,44.6 ; C34.1@44.062,44.923 42.725,44.6 ; C34.1@44.138,44.277 45.475,44.6 C34.1@44.138,44.923 ; R37.2@45.71,44.313 C34.1@44.429,44.853 ; R37.2@45.71,44.887 C34.1@44.429,44.347 ; R37.2@45.762,44.277 C34.1@44.425,44.6 ; R37.2@45.762,44.923 C34.1@44.425,44.6 ; R37.2@45.8,44.575 C34.1@44.429,44.347 ; R37.2@45.8,44.625 C34.1@44.429,44.853 ; R37.2@45.815,44.25 C34.1@44.429,44.347 ; R37.2@45.815,44.95 C34.1@44.429,44.853 ; v1(34.5,44.7) U7.6@35.45,44.7 ; v1(34.5,44.7) 35.434,44.874 v1(34.5,44.7) ; v1(34.5,44.7) 35.434,44.526 v1(34.5,44.7) ; v1(34.5,44.7) U7.6@35.45,44.7 ; v1(34.5,44.7) 35.1,44.7 ; v1(34.5,44.7) U7.6@35.45,44.7 ; 35.1,44.7 U7.6@35.45,44.7 ; TP10.1@41.7,44.6 42.725,44.6 ; TP10.1@41.7,44.6 42.725,44.6 ; TP10.1@41.7,44.6 42.725,44.6 ; TP10.1@41.735,44.336 42.725,44.6 ; TP10.1@41.735,44.336 42.725,44.6 ; TP10.1@41.735,44.336 42.725,44.6 ; TP10.1@41.735,44.864 42.725,44.6 ; TP10.1@41.735,44.864 42.725,44.6 ; TP10.1@41.735,44.864 42.725,44.6 ; TP10.1@41.856,44.056 42.725,44.6 ; TP10.1@41.856,44.056 42.725,44.6 ; TP10.1@41.856,44.056 42.725,44.6 ; TP10.1@41.856,45.144 42.725,44.6 ; TP10.1@41.856,45.144 42.725,44.6 ; TP10.1@41.856,45.144 42.725,44.6 ; TP10.1@42.066,43.815 42.725,44.6 ; TP10.1@42.066,43.815 42.725,44.6 ; TP10.1@42.066,43.815 42.725,44.6 ; TP10.1@42.066,45.385 42.725,44.6 ; TP10.1@42.066,45.385 42.725,44.6 ; TP10.1@42.066,45.385 42.725,44.6 ; 42.725,44.6 C34.1@44.1,44.6 ; C34.1@44.1,44.6 R37.2@45.8,44.6 C34.1@44.425,44.6
  Bottom Layer w0.3: v1(34.5,44.7) 41.6,44.7 TP10.1@41.7,44.6
M1_BEMF_VB: C35.1 R38.2 TP11.1 U1.8 U7.3 | length 83.1
  Top Layer w0.3: U1.8@21.7,47.55 24.15,47.55 25.8,45.9 25.8,41.4 28.3,38.9 v1(36.3,38.9) ; U1.8@22.25,47.55 23.3,47.55 ; U7.3@37.176,42.056 37.35,41.25 ; U7.3@37.35,42.075 37.35,41.25 ; U7.3@37.35,42.3 37.35,41.25 ; U7.3@37.524,42.056 37.35,41.25 ; C35.1@44.062,40.377 42.725,40.7 ; C35.1@44.062,41.023 42.725,40.7 ; C35.1@44.138,40.377 45.475,40.7 C35.1@44.138,41.023 ; R38.2@45.71,40.413 C35.1@44.429,40.953 ; R38.2@45.71,40.987 C35.1@44.429,40.447 ; R38.2@45.762,40.377 C35.1@44.425,40.7 ; R38.2@45.762,41.023 C35.1@44.425,40.7 ; R38.2@45.8,40.675 C35.1@44.429,40.447 ; R38.2@45.8,40.725 C35.1@44.429,40.953 ; R38.2@45.815,40.35 C35.1@44.429,40.447 ; R38.2@45.815,41.05 C35.1@44.429,40.953 ; 37.35,41.25 37.9,40.7 TP11.1@41.6,40.7 ; TP11.1@41.6,40.7 42.725,40.7 ; TP11.1@41.6,40.7 42.725,40.7 ; TP11.1@41.6,40.7 42.725,40.7 ; TP11.1@41.6,40.7 C35.1@44.1,40.7 ; TP11.1@41.631,40.436 42.725,40.7 ; TP11.1@41.631,40.436 42.725,40.7 ; TP11.1@41.631,40.436 42.725,40.7 ; TP11.1@41.631,40.964 42.725,40.7 ; TP11.1@41.631,40.964 42.725,40.7 ; TP11.1@41.631,40.964 42.725,40.7 ; TP11.1@41.742,40.152 42.725,40.7 ; TP11.1@41.742,40.152 42.725,40.7 ; TP11.1@41.742,40.152 42.725,40.7 ; TP11.1@41.742,41.248 42.725,40.7 ; TP11.1@41.742,41.248 42.725,40.7 ; TP11.1@41.742,41.248 42.725,40.7 ; TP11.1@41.933,39.901 42.725,40.7 ; TP11.1@41.933,39.901 42.725,40.7 ; TP11.1@41.933,39.901 42.725,40.7 ; TP11.1@41.933,41.499 42.725,40.7 ; TP11.1@41.933,41.499 42.725,40.7 ; TP11.1@41.933,41.499 42.725,40.7 ; 42.725,40.7 C35.1@44.1,40.7 ; C35.1@44.1,40.7 R38.2@45.8,40.7 C35.1@44.425,40.7
  Bottom Layer w0.3: v1(36.3,38.9) 38.1,40.7 TP11.1@41.6,40.7
M1_BEMF_VC: C36.1 R39.2 TP12.1 U1.30 U7.4 | length 37.2
  Top Layer w0.3: U1.30@29.7,46.9 31.1,46.9 ; U1.30@30.25,46.9 31.1,46.9 ; U7.4@37.35,44.7 37.35,47.55 ; 37.9,47.6 37.3,47.6 ; TP12.1@42.3,47.6 TP12.1@41.4,47.6 ; C36.1@44.138,48.177 45.475,48.5 C36.1@44.138,48.823 ; R39.2@45.71,48.213 C36.1@44.429,48.753 ; R39.2@45.71,48.787 C36.1@44.429,48.247 ; R39.2@45.762,48.177 C36.1@44.425,48.5 ; R39.2@45.762,48.823 C36.1@44.425,48.5 ; R39.2@45.8,48.475 C36.1@44.429,48.247 ; R39.2@45.8,48.525 C36.1@44.429,48.753 ; R39.2@45.815,48.15 C36.1@44.429,48.247 ; R39.2@45.815,48.85 C36.1@44.429,48.753 ; 31.1,46.9 31.8,47.6 37.3,47.6 ; 37.3,47.6 37.35,47.55 ; 37.35,47.55 37.4,47.6 TP12.1@41.4,47.6 ; TP12.1@41.4,47.6 42.3,48.5 C36.1@44.1,48.5 R39.2@45.8,48.5 C36.1@44.425,48.5
M1_DC_CAL: J10.2 TP1.1 U1.34 | length 47.9
  Top Layer w0.3: U1.34@29.7,49.5 32,49.5 33.3,50.8 TP1.1@40.6,50.8 ; U1.34@30.25,49.5 31.3,49.5 ; TP1.1@40.6,50.9 40.6,53.3 44.3,57 52.2,57 56.1,60.9 J10.2@61.9,60.9 ; J10.2@61.739,61.63 60.195,60.9 ; J10.2@61.814,60.356 60.195,60.9 ; J10.2@61.844,61.345 60.195,60.9 ; J10.2@61.885,60.65 60.195,60.9 ; J10.2@61.9,61 60.195,60.9
M1_EN_GATE: U1.3 U5.12 | length 52.1
  Top Layer w0.3: U1.3@21.7,50.8 22.8,50.8 ; U1.3@22.25,50.8 22.8,50.8 ; v1(23.9,51.9) 22.8,50.8 ; v1(58,58.3) 59,57.3 59,56 61.25,53.75 U5.12@61.25,49.225 ; U5.12@61.25,49.95 61.25,51
  Bottom Layer w0.3: v1(23.9,51.9) 31.1,59.1 57.2,59.1 v1(58,58.3)
M1_FET_TEMP: C31.1 TP6.1 U1.11 U6.3 | length 54.8
  Top Layer w0.3: U1.11@21.7,45.6 24.2,45.6 25,44.8 25,40.3 28.1,37.2 TP6.1@37.5,37.2 TP6.1@38.1,37.2 ; U1.11@22.25,45.6 23.3,45.6
  Top Layer w0.4: C31.1@51.328,31.242 v1(51.6,32.1) ; C31.1@51.353,31.158 U6.3@51.75,29.506 ; C31.1@51.403,30.95 U6.3@51.75,29.575 ; C31.1@51.625,31.2 U6.3@51.75,29.506 ; C31.1@51.642,30.973 U6.3@51.75,29.575 ; U6.3@51.75,29.35 51.75,31.05 C31.1@51.6,31.2 v1(51.6,32.1) ; C31.1@51.75,30.975 U6.3@51.75,29.575 ; C31.1@51.872,31.242 v1(51.6,32.1) ; C31.1@51.88,30.971 U6.3@51.75,29.575 ; C31.1@51.9,31.198 U6.3@51.75,29.506
  Bottom Layer w0.4: TP6.1@38.1,37.2 41.5,33.8 50.4,33.8 51.6,32.6 v1(51.6,32.1)
M1_GH_A: Q1.2 R20.2 | length 8.1
  Top Layer w0.5: R20.2@69.3,29.775 70.345,28.755 ; R20.2@69.3,29.8 70.345,28.755 ; Q1.2@70.345,25.366 70.345,28.755 ; Q1.2@70.345,26.091 70.345,27.891
M1_GH_B: Q2.2 R22.2 | length 8.8
  Top Layer w0.5: Q2.2@58.735,25.4 R22.2@58.735,29.635 ; 58.735,27.769 R22.2@58.9,29.775 ; 58.735,27.891 Q2.2@58.745,26.091 ; R22.2@58.735,30.135 R22.2@58.735,29.635 ; R22.2@58.9,29.8 R22.2@58.735,29.635
M1_GH_C: Q3.2 R25.2 | length 6.6
  Top Layer w0.5: R25.2@45.975,28.7 45,28.7 ; R25.2@46,28.7 45,28.7 ; 44.035,27.735 44.045,26.091 44.035,26.4 44.035,27.735 ; 44.035,27.735 45,28.7
M1_GL_A: Q1.4 R21.2 | length 8.1
  Top Layer w0.5: R21.2@65.2,29.675 65.2,28.8 ; R21.2@65.2,29.7 65.2,28.8 ; 66.467,27.533 Q1.4@67.805,26.091 ; Q1.4@67.895,25.6 67.895,26.105 65.2,28.8
M1_GL_B: Q2.4 R23.2 | length 9.6
  Top Layer w0.5: 55.5,27.651 R23.2@56,29.775 ; R23.2@56,29.8 55.5,29.3 ; Q2.4@56.205,25.366 56.205,26.195 55.5,26.9 ; Q2.4@56.205,26.091 55.5,26.9 ; 55.5,26.9 55.5,29.3 ; 55.5,29.3 R23.2@56,29.775 ; 55.5,29.3 R23.2@56,29.775
M1_GL_C: Q3.4 R28.2 | length 8.8
  Top Layer w0.5: 40.864,28.264 R28.2@42.4,29.775 ; Q3.4@41.495,25.3 41.495,26.1 40.7,26.895 ; Q3.4@41.505,26.091 40.7,26.895 ; R28.2@42.4,29.8 40.7,28.1 40.7,26.895
M1_IDC: D8.2 U1.23 U5.21 | length 37.8
  Top Layer w0.3: U1.23@29.7,42.35 31.25,42.35 ; U1.23@30.25,42.35 31.25,42.35 ; v1(32.2,43.3) 31.25,42.35 ; v1(43.3,52.6) 46,52.6 46.4,53 50.1,53 ; v1(50.1,51.9) 50.1,53 ; D8.2@50.4,54.2 50.1,53.9 50.1,53 ; v1@54.2,51 54.5,51.3 55.8,51.3 56.75,50.35 ; U5.21@56.75,49.225 56.75,50.35 ; U5.21@56.75,49.95 56.75,50.35
  Bottom Layer w0.3: v1(32.2,43.3) 32.2,45 39.8,52.6 v1(43.3,52.6) ; 50.5,51.9 52.4,51.9 53.3,51 v1(54.1,51)
M1_INH_A: U1.37 U5.13 | length 42.8
  Top Layer w0.3: U1.37@29.7,51.45 30.975,51.45 ; U1.37@30.25,51.45 30.975,51.45 ; v1(32.2,53.2) 32.2,52.675 30.975,51.45 ; v1(57.2,57.7) 58.1,56.8 58.1,56 60.75,53.35 U5.13@60.75,49.225 ; U5.13@60.75,49.95 60.75,51
  Bottom Layer w0.3: v1(32.2,53.2) 37.5,58.5 56.4,58.5 v1(57.2,57.7)
M1_INH_B: U1.33 U5.15 | length 41.8
  Top Layer w0.3: U1.33@29.7,48.85 31.35,48.85 v1@31.5,48.7 ; U1.33@30.25,48.85 v1@31.3,48.85 ; v1(54.8,56.8) 55.9,56.8 56.3,56.4 56.3,56.1 59.75,52.65 U5.15@59.75,49.225 ; U5.15@59.75,49.95 59.75,51
  Bottom Layer w0.3: v1(31.4,48.6) 31.4,49.9 38.3,56.8 v1(54.8,56.8)
M1_INH_C: U1.29 U5.17 | length 38.5
  Top Layer w0.3: U1.29@29.7,46.25 31.65,46.25 v1(32.1,46.7) ; U1.29@30.25,46.25 31.3,46.25 ; v1@55.7,54.8 55.8,54.8 58.75,51.85 U5.17@58.75,49.225 ; U5.17@58.75,49.95 58.75,51
  Bottom Layer w0.3: v1(32.1,46.7) 40.2,54.8 v1@55.7,54.8
  other v1: 55.7,54.7
M1_INL_A: U1.20 U5.14 | length 53.3
  Top Layer w0.3: U1.20@29.7,40.4 30.7,40.4 ; U1.20@30.25,40.4 30.7,40.4 ; v1(31.2,39.9) 30.7,40.4 ; v1@57.2,56.6 v1(57.2,56.5) 57.2,56.1 60.25,53.05 U5.14@60.25,49.225 ; U5.14@60.25,49.95 60.25,51
  Bottom Layer w0.3: v1(31.2,39.9) 29.7,41.4 29.7,49.2 38.2,57.7 56,57.7 v1(57.2,56.5)
M1_INL_B: U1.21 U5.16 | length 47.7
  Top Layer w0.3: U1.21@29.7,41.05 31.55,41.05 v1(31.8,40.8) ; U1.21@30.25,41.05 31.3,41.05 ; v1@55.5,56 59.25,52.25 U5.16@59.25,49.225 ; U5.16@59.25,49.95 59.25,51
  Bottom Layer w0.3: v1(31.8,40.8) 30.5,42.1 30.5,46.4 40,55.9 v1(55.5,55.9)
M1_INL_C: U1.22 U5.18 | length 41.8
  Top Layer w0.3: U1.22@29.7,41.7 30.9,41.7 ; U1.22@30.25,41.7 30.9,41.7 ; v1(32.2,41.7) 30.9,41.7 ; v1(55.6,53.6) 56.2,53.6 58.25,51.55 U5.18@58.25,49.225 ; U5.18@58.25,49.95 58.25,51
  Bottom Layer w0.3: v1(32.2,41.7) 32.1,41.6 31.2,42.5 31.2,44.8 40,53.6 v1(55.6,53.6)
M1_NFAULT: R17.1 U1.36 U5.2 | length 60.5
  Top Layer w0.3: U1.36@29.7,50.8 31.3,50.8 ; U1.36@30.25,50.8 31.3,50.8 ; v1(54.6,63.2) 49.9,58.5 43.7,58.5 38.6,53.4 33.9,53.4 31.3,50.8 ; U5.2@66.25,49.225 66.25,50.25 ; U5.2@66.25,49.95 66.25,50.25 ; R17.1@68.2,56.1 68.5,55.8 v1(68.5,55.1) ; R17.1@68.276,56.054 v1(68.5,55.1) ; R17.1@68.6,56.075 v1(68.5,55.1) ; R17.1@68.913,55.989 v1(68.5,55.1) ; 66.25,50.25 67,51 67.7,51 68,51.3 68,54.6 v1(68.5,55.1)
  Bottom Layer w0.3: v1(54.6,63.2) 57.9,63.2 62,59.1 65.5,59.1 68.5,56.1 v1(68.5,55.1)
M1_NOCTW: R16.1 U1.35 U5.1 | length 64.2
  Top Layer w0.3: U1.35@29.7,50.15 31.65,50.15 34.3,52.8 39.1,52.8 44.1,57.8 52,57.8 57.1,62.9 67.6,62.9 71.2,59.3 71.2,56.4 70.9,56.1 ; U1.35@30.25,50.15 31.3,50.15 ; U5.1@66.75,49.225 U5.1@66.75,49.95 ; R16.1@70.275,55.784 70.9,56.1 ; R16.1@70.275,56.416 70.9,56.1 ; U5.1@66.75,49.95 67.2,50.4 ; U5.1@66.75,49.95 67.2,50.4 ; 67.2,50.4 68,50.4 68.6,51 68.6,53.4 70.2,55 R16.1@70.2,56.1 70.9,56.1
M1_NSCS: U1.10 U5.4 | length 71.5
  Top Layer w0.3: v1(18.8,46.7) 19.25,46.25 U1.10@21.7,46.25 ; 20.1,46.25 U1.10@21.15,46.25 ; U5.4@65.25,49.225 65.25,50.95 ; U5.4@65.25,49.95 65.25,50.95 ; v1(66.7,52.4) 65.25,50.95
  Bottom Layer w0.3: v1(18.8,46.7) 18.8,49.6 32,62.8 41.2,62.8 41.9,62.1 57.9,62.1 61.7,58.3 64.3,58.3 66.7,55.9 v1(66.7,52.4)
M1_OUT_A: C22.1 L5.1 Q1.1 Q1.5 Q1.6 R33.2 U5.42 | length 79.8
  Top Layer w0.3: R33.2@49.2,44.6 v1(50.2,44.6) ; R33.2@49.253,44.279 v1(50.2,44.6) ; R33.2@49.253,44.921 v1(50.2,44.6) ; 63.75,40.2 U5.42@63.75,41.25 ; U5.42@63.75,41.975 63.75,39.55 v1(65.8,37.5) 66.6,37.5 67,37.1 67,34.7 67.5,34.2 ; C22.1@68.447,33.879 67.5,34.2 ; C22.1@68.447,34.521 67.5,34.2 ; C22.1@68.5,34.2 67.5,34.2
  Top Layer w0.5: 65.1,17 v1@65.9,17 ; 65.4,17.1 v1@66,17.1 ; v1@66.005,17.105 v1@66,17.1 ; v1@66.105,17.105 66.1,17.1 v1@66,17.1 ; L5.1@66.9,14.685 67.995,15.78 L5.1@67.6,14.485 ; Q1.5@67.805,19.291 67.895,17.49 ; Q1.5@67.895,20.8 67.895,17 ; v1@68,17 67.895,17 ; C22.1@68.5,34.175 70.272,32.928 ; Q1.6@69.075,19.291 v1@69.165,17.95 ; Q1.6@69.075,20.741 69.165,22.543 ; Q1.1@71.615,24.641 71.705,23.905 ; Q1.1@71.615,25.366 71.615,28.885 70.6,29.9 70.6,32.6 69,34.2 ; Q1.1@71.615,26.091 71.615,27.891 ; Q1.1@71.705,25.366 71.705,23.905 ; v1@65.9,17 v1@66,17.1 ; v1@65.9,17 v1(66,17) v1(67.2,17) 67.895,17 ; 67.895,17 67.895,16.68 v1@69.165,17.95 ; 69,34.2 C22.1@68.5,34.2 69,34.2 ; v1@69.165,17.95 69.165,22.565 69.9,23.3 71.1,23.3 71.705,23.905
  Top Layer w1: v1@66.1,17.1 67.6,17.1
  Bottom Layer w0.3: v1(50.2,44.6) 53.4,41.4 58.5,41.4 62.4,37.5 v1(65.8,37.5)
  Bottom Layer w1: 65.3,17.1 v1@65.9,17.1
  other v1: 65.2,14.5 70.1,14.7 64.8,15.2 67.9,15.9 66.7,16 68.8,16 65.4,16.2 69.8,16.2 64.8,17 68.2,17 69.3,17 70.3,17 65.4,17.7 66.6,17.8 67.7,17.9 69,17.9 64.9,18.6 66,18.6 67.2,18.6 68.4,18.6
M1_OUT_B: C25.1 L6.1 Q2.1 Q2.5 Q2.6 R34.2 U5.37 | length 68.9
  Top Layer w0.3: R34.2@49.288,40.387 49.8,40.7 ; R34.2@49.288,41.013 49.8,40.7 ; v1(51.4,40.7) 49.8,40.7 ; Q2.1@60.005,25.4 60.005,31 61,31.995 62.695,31.995 63.3,32.6 C25.1@63.3,34.2 61.925,34.2 ; 60.005,27.291 Q2.1@60.015,26.091 ; 61.25,40.2 U5.37@61.25,41.25 ; U5.37@61.25,41.975 61.25,37.4 61.4,37.25 61.4,34.7 61.9,34.2 C25.1@63,34.2 ; C25.1@62.977,34.137 63.3,32.8 ; C25.1@63.262,33.877 61.925,34.2 ; C25.1@63.262,34.523 61.925,34.2 ; C25.1@63.3,34.175 63.3,32.8 ; C25.1@63.623,34.137 63.3,32.8
  Top Layer w0.5: 56.195,17.491 Q2.5@56.205,19.291 ; Q2.5@56.195,20.6 56.195,17.39 57.465,16.12 57.465,22.465 ; L6.1@56.7,14.485 57.565,15.22 L6.1@58.1,14.685 ; 57.465,17.491 Q2.6@57.475,19.291 ; Q2.6@57.475,20.741 57.465,22.465 ; Q2.1@60.005,25.4 60.005,23.905 ; Q2.1@60.015,24.641 60.005,23.905 ; 57.465,22.465 58,23 59.1,23 60.005,23.905
  Bottom Layer w0.3: v1(51.4,40.7) 57.5,40.7 60.8,37.4 v1(61.4,37.4)
  other v1: 53.2,16.4 54.5,16.4 55.6,16.4 56.7,16.4 57.7,16.4 58.9,16.4 58.3,17.1 53.9,17.2 55.1,17.2 56.1,17.2 57.3,17.2 52.9,17.3 55.1,18.1 52.8,18.2 53.9,18.2 56.2,18.2 57.4,18.2 53.3,18.9 54.6,18.9 55.5,18.9
M1_OUT_C: C26.1 L7.1 Q3.1 Q3.5 Q3.6 R35.2 U5.32 | length 68.8
  Top Layer w0.3: Q3.1@45.305,25.3 45.305,26.805 ; Q3.1@45.315,26.091 45.305,26.805 ; R35.2@48.88,48.421 v1(49.2,47.5) ; R35.2@49.2,48.475 v1(49.2,47.5) ; R35.2@49.2,48.5 v1(49.2,47.5) ; R35.2@49.52,48.421 v1(49.2,47.5) ; C26.1@57.477,35.863 57.8,37.2 ; C26.1@57.8,35.825 57.8,37.2 ; C26.1@58.123,35.863 57.8,37.2 ; 58.75,40.2 U5.32@58.75,41.25 ; U5.32@58.75,41.975 58.75,39.25 v1(57.8,38.3) C26.1@57.8,35.8 56.7,34.7 56.7,33.7 56.1,33.1 51.6,33.1 48.7,30.2 48.7,27.9 48,27.2 45.7,27.2 45.305,26.805
  Top Layer w0.5: Q3.6@42.775,19.291 v1(42.765,18.4) ; Q3.6@42.775,20.741 42.765,22.365 ; Q3.1@45.305,25.3 45.305,23.805 ; 45.315,15.485 42.765,18.035 v1(42.765,18.4) ; Q3.1@45.315,24.641 45.305,23.805 ; v1(42.765,18.4) 42.765,22.365 ; 42.765,22.365 43.5,23.1 44.6,23.1 45.305,23.805
  Bottom Layer w0.3: v1(49.2,47.5) 49.2,40.7 49.9,40 56.8,40 57.8,39 v1(57.8,38.3)
  other v1: 40.7,15.6 41.7,15.6 44.1,15.6 45.1,15.7 46.4,15.7 47.5,15.7 48,16.2 43.4,16.5 44.6,16.5 45.8,16.5 47,16.5 39.5,17.4 40.6,17.5 41.6,17.5 42.8,17.6 39.6,18.4 40.6,18.4 41.6,18.4 39.6,19.3 40.6,19.3 39.6,20.3 40.5,20.3
M1_SCLK: R15.1 U1.9 | length 57
  Top Layer w0.3: v1(19.9,47.3) 20.3,46.9 ; U1.9@21.15,46.9 20.3,46.9 ; U1.9@21.7,46.9 20.3,46.9 ; v1(57.1,59.9) 60.5,59.9 R15.1@62.3,58.1 ; R15.1@62.05,57.918 61.189,59.211 ; R15.1@62.3,58.125 61.189,59.211 ; R15.1@62.502,58.38 61.189,59.211
  Bottom Layer w0.3: v1(19.9,47.3) 19.9,49.3 30.5,59.9 v1(57.1,59.9)
M1_SDI: R18.1 U1.5 | length 61.6
  Top Layer w0.3: U1.5@21.7,49.5 25.2,49.5 26.9,51.2 26.9,57.7 30.8,61.6 v1(37.9,61.6) ; U1.5@22.25,49.5 23.3,49.5 ; v1(63.4,56.5) 65.4,54.5 R18.1@65.4,54.4 ; R18.1@65.141,54.229 64.325,55.575 ; R18.1@65.4,54.425 64.325,55.575 ; R18.1@65.613,54.67 64.325,55.575
  Bottom Layer w0.3: v1(37.9,61.6) 38.2,61.9 40.4,61.9 41,61.3 57.8,61.3 61.4,57.7 62.2,57.7 v1(63.4,56.5)
M1_SDO: R45.1 U1.6 | length 56.9
  Top Layer w0.3: U1.6@21.7,48.85 25.477,48.85 27.656,51.028 27.656,56.756 31.7,60.8 v1(39.2,60.8) ; U1.6@22.25,48.85 23.3,48.85 ; v1(63.2,55.5) 63.5,55.2 ; R45.1@63.48,54.369 63.5,55.2 ; R45.1@63.8,54.4 63.5,54.7 63.5,55.2 ; R45.1@63.8,54.425 63.5,55.2 ; R45.1@64.074,54.599 63.5,55.2
  Bottom Layer w0.3: v1(39.2,60.8) 39.4,60.6 57.6,60.6 61.1,57.1 61.6,57.1 v1(63.2,55.5)
M1_SL: C16.1 C17.1 C18.1 Q1.3 Q2.3 Q3.3 R8.2 R24.2 U5.30 U5.35 U5.40 | length 110.9
  Top Layer w0.3: Q3.3@42.765,25.3 Q3.3@42.8,25.335 ; v1@42.8,27.3 v1(42.8,28.2) 43.2,28.6 43.7,28.6 44.9,29.8 46.7,29.8 51.5,34.6 v1(55.9,34.6) ; C16.1@47.7,24.016 C16.1@47.7,24.1 ; v1@56.2,36.6 56.2,38.5 57.75,40.05 U5.30@57.75,41.975 ; Q2.3@57.43,25.365 57.465,25.4 Q2.3@57.5,25.435 ; v1@57.465,27.365 v1(57.465,28.265) ; 57.5,27.3 57.5,32.3 60.25,35.05 U5.35@60.25,41.975 ; 57.75,40.2 U5.30@57.75,41.25 ; 60.25,40.2 U5.35@60.25,41.25 ; 62.75,40.2 U5.40@62.75,41.25 ; U5.40@62.75,41.975 62.75,38.85 64.35,37.25 64.35,33.65 64.7,33.3 65.4,33.3 68.1,30.6 68.1,27.8 ; Q1.3@69.13,25.565 Q1.3@69.165,25.6 ; v1@69.165,27.565 v1(69.165,28.465) ; R8.2@74.4,34 76.3,34 77.9,32.4 77.9,28.5 77.7,28.3 76,28.3 ; R8.2@74.425,34 75.8,34 ; R8.2@74.463,33.677 75.8,34 ; R8.2@74.463,34.323 75.8,34
  Top Layer w0.5: Q3.3@42.775,26.091 42.8,27.3 Q3.3@42.8,25.335 ; Q2.3@57.465,25.4 57.465,27.365 57.475,26.091 57.5,27.3 Q2.3@57.5,25.435
  Bottom Layer w0.3: v1(55.9,34.6) 56.2,34.9 v1(56.2,36.4)
  Bottom Layer w1: 44.4,27.3 v1@69.2,27.3
  other v1: 73.6,22.1 72.9,22.4 73.7,23 72.9,23.3 49,23.8 63.7,23.8 73.2,24 49,24.6 63.7,24.7 47.3,25.3 48.2,25.3 61.9,25.3 62.8,25.3 49,25.4 63.7,25.5 47.7,26 48.6,26 62.3,26.2 63.3,26.2 43,26.8 57.665,26.865 42.2,27 56.865,27.065 69.365,27.065 68.565,27.265 73.8,27.3 43,27.5 57.665,27.565 69.365,27.765 73,27.8 42.2,27.9 56.865,27.965 68.565,28.165 73.8,28.2 73,28.7 73.8,29.2 73.1,29.6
